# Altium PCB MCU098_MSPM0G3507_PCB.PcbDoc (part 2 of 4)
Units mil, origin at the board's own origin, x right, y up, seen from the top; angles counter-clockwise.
Board outline 2310.03 x 4205.03 mil, 4 copper layers (Top Layer, VCC Layer, GND Layer, Bottom Layer), stack 62.4 mil thick; 260 components, 182 nets, 835 pads, 237 vias.
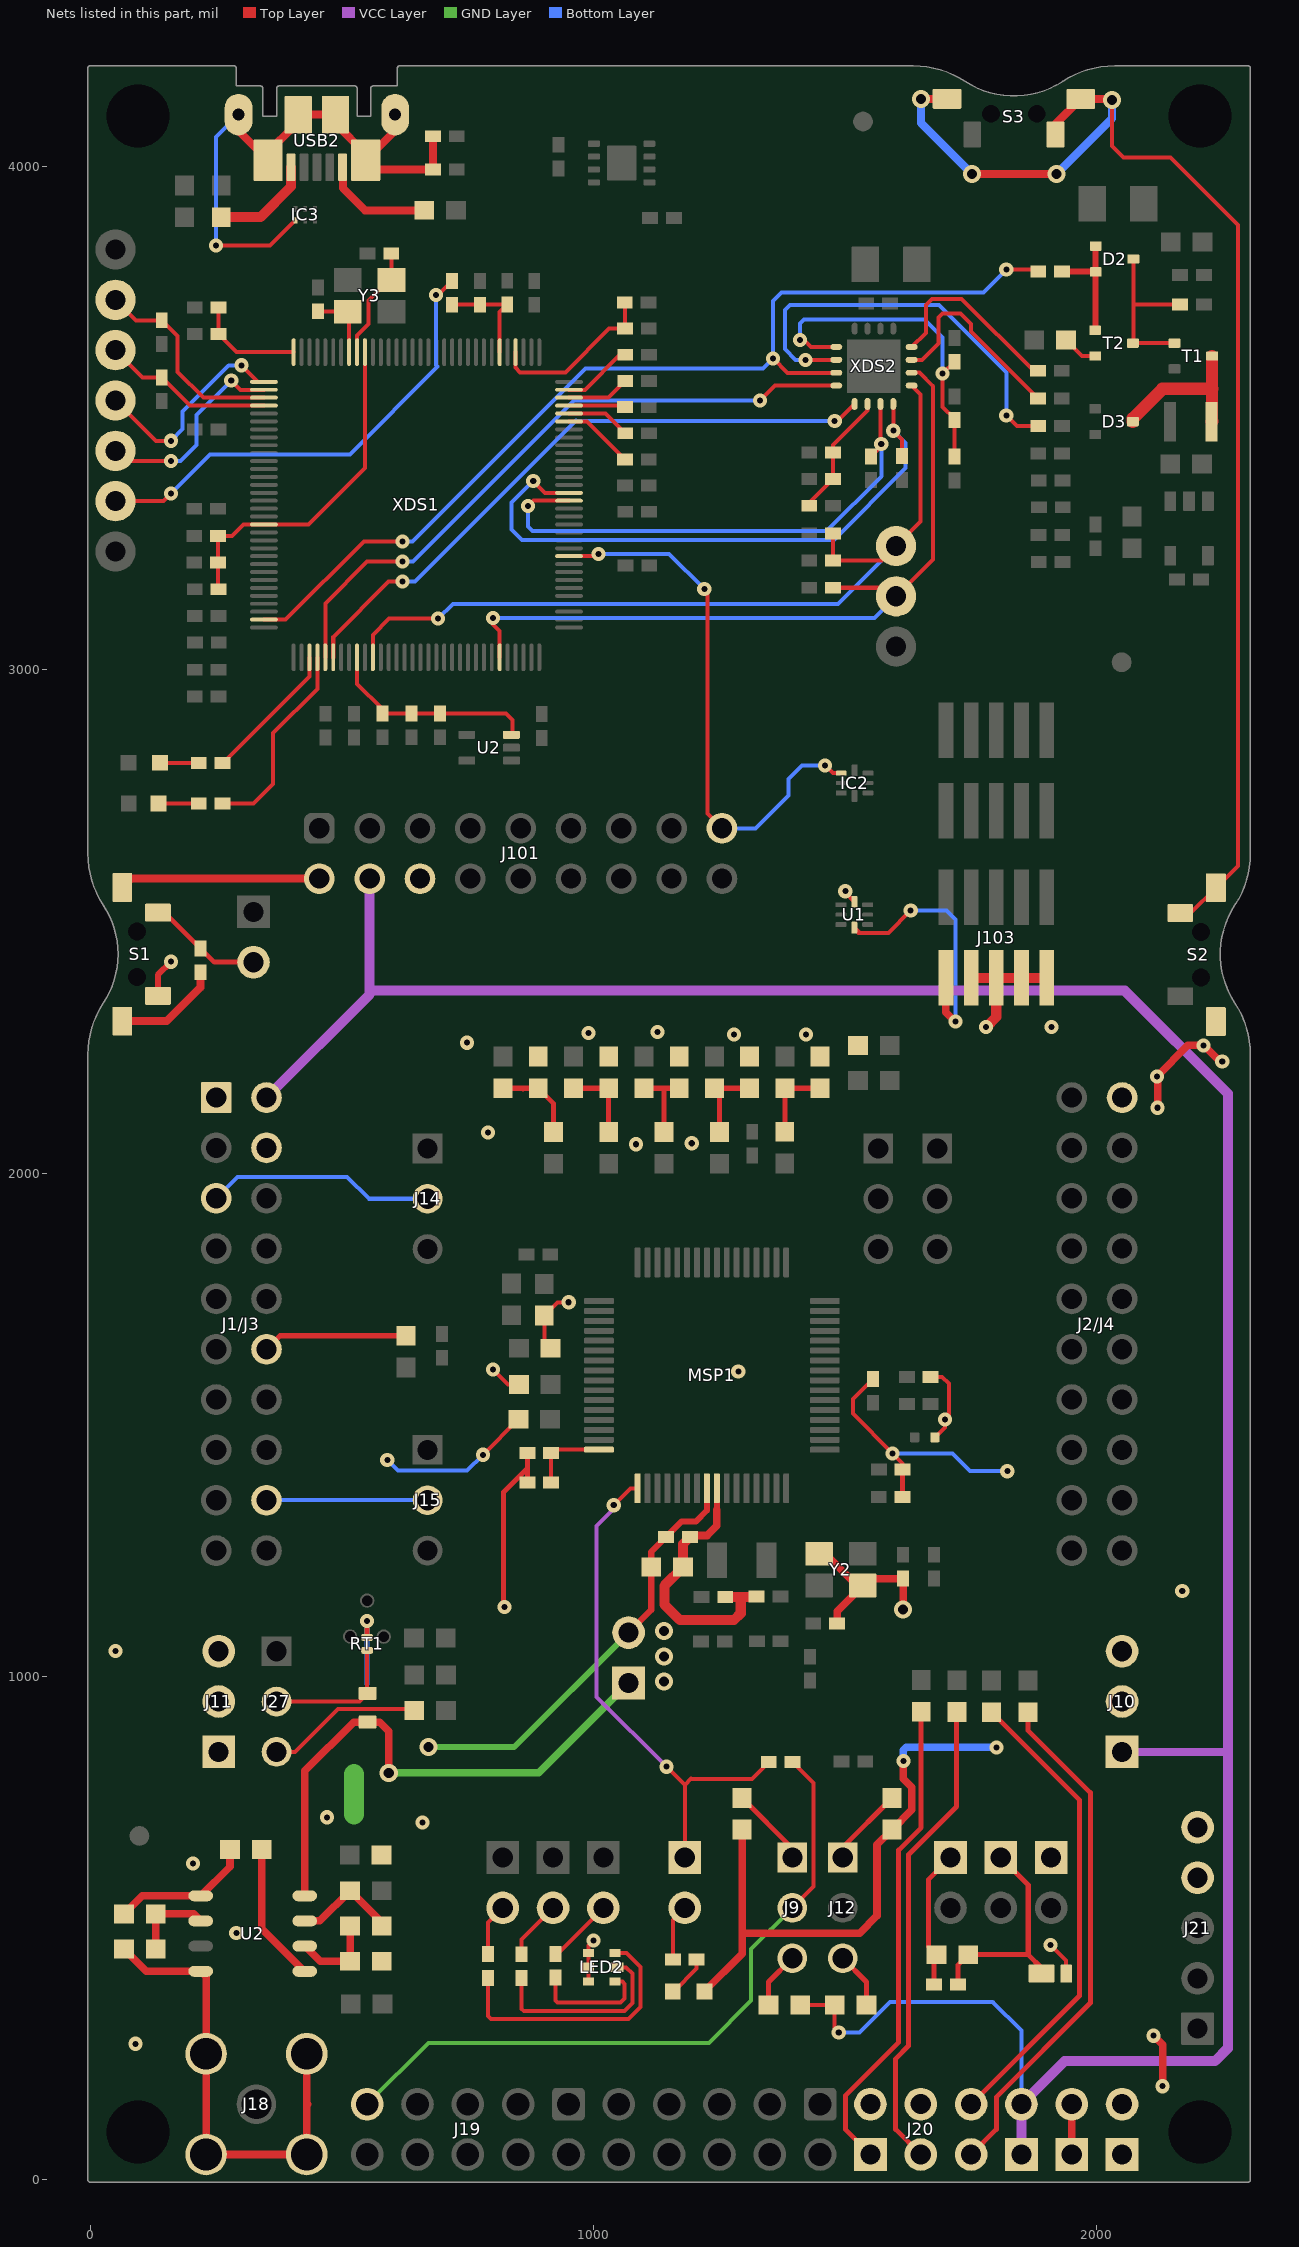
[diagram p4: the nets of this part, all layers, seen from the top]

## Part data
C1: library part CMP-0007304-1, "CAP, CERM, 10 uF, 6.3 V, +/- 20%, X5R, 0603", Cap_Case=0603, Manufacturer=MuRata, Supplier Part Number 1=490-7316-1-ND, TempCo=X5R, Tolerance_%=20%, Value1=Unknown, Value2=6.3V, ValueDisplayed=10uF
C2: library part CMP-0006614-2, "CAP, CERM, 0.1 uF, 50 V, +/- 20%, X5R, 0402", Cap_Case=0402, Manufacturer=MuRata, Supplier Part Number 1=GRM155R61H104ME14D-ND, TempCo=X5R, Tolerance_%=20%, Value1=Unknown, Value2=50V, ValueDisplayed=0.1uF
C3: library part CMP-0006551-2, "CAP, CERM, 0.47 uF, 6.3 V, +/- 10%, X5R, 0402", Cap_Case=0402, Manufacturer=MuRata, Supplier Part Number 1=490-3266-1-ND, TempCo=X5R, Tolerance_%=10%, Value1=Unknown, Value2=6.3V, ValueDisplayed=0.47uF
C4: library part CMP-0006614-2, "CAP, CERM, 0.1 uF, 50 V, +/- 20%, X5R, 0402", Cap_Case=0402, Manufacturer=MuRata, Supplier Part Number 1=GRM155R61H104ME14D-ND, TempCo=X5R, Tolerance_%=20%, Value1=Unknown, Value2=50V, ValueDisplayed=DNC
C5: library part CMP-0006388-2, "CAP, CERM, 47 pF, 25 V, +/- 5%, C0G/NP0, 0402", Cap_Case=0402, Manufacturer=MuRata, Supplier Part Number 1=81-GRM1555C1E470JA1D, TempCo=C0G/NP0, Tolerance_%=5%, Value1=Unknown, Value2=25V, ValueDisplayed=47pF
C6: library part CMP-0006590-2, "CAP, CERM, 0.01 uF, 16 V, +/- 10%, X5R, 0402", Cap_Case=0402, Manufacturer=MuRata, Supplier Part Number 1=GRM155R61C103KA01D-ND, TempCo=X5R, Tolerance_%=10%, Value1=Unknown, Value2=16V, ValueDisplayed=0.01uF
C7 C8: library part CMP-0007006-5, "CAP, CERM, 1 uF, 25 V, +/- 10%, X5R, 0603", Cap_Case=0603, Manufacturer=TDK, Supplier Part Number 1=445-5146-1-ND, TempCo=X5R, Tolerance_%=10%, Value1=Unknown, Value2=25V, ValueDisplayed=DNC
C9 C10 C11 C12: library part CMP-0006439-2, "CAP, CERM, 22 pF, 50 V, +/- 5%, C0G/NP0, 0402", Cap_Case=0402, Manufacturer=MuRata, Supplier Part Number 1=81-GRM1555C1H220JA1D, TempCo=C0G/NP0, Tolerance_%=5%, Value1=Unknown, Value2=50V, ValueDisplayed=22pF
C13 C17 C18 C20 C24 C27 C28 C33 C38 C39 C44: library part CMP-0006623-2, "CAP, CERM, 0.1 uF, 6.3 V, +/- 10%, X7R, 0402", Cap_Case=0402, Manufacturer=MuRata, Supplier Part Number 1=GRM155R70J104KA01D-ND, TempCo=X7R, Tolerance_%=10%, Value1=Unknown, Value2=6.3V, ValueDisplayed=0.1uF
C14 C15 C16 C22 C26: library part CMP-0006658-2, "CAP, CERM, 0.01 uF, 25 V, +/- 10%, X7R, 0402", Cap_Case=0402, Manufacturer=MuRata, Supplier Part Number 1=490-1312-1-ND, TempCo=X7R, Tolerance_%=10%, Value1=Unknown, Value2=25V, ValueDisplayed=0.01uF
C19 C21 C25 C55: library part CMP-0006276-2, "CAP, CERM, 1 uF, 25 V, +/- 10%, X5R, 0402", Cap_Case=0402, Manufacturer=TDK, Supplier Part Number 1=445-9066-1-ND, TempCo=X5R, Tolerance_%=10%, Value1=Unknown, Value2=25V, ValueDisplayed=1uF
C23 C56: library part CMP-0006543-2, "CAP, CERM, 2.2 uF, 6.3 V, +/- 10%, X5R, 0402", Cap_Case=0402, Manufacturer=MuRata, Supplier Part Number 1=81-GRM155R60J225KE5D, TempCo=X5R, Tolerance_%=10%, Value1=Unknown, Value2=6.3V, ValueDisplayed=2.2uF
C29 C30: library part CMP-0006415-2, "CAP, CERM, 12 pF, 50 V, +/- 5%, C0G/NP0, 0402", Cap_Case=0402, Manufacturer=MuRata, Supplier Part Number 1=14T3292, TempCo=C0G/NP0, Tolerance_%=5%, Value1=Unknown, Value2=50V, ValueDisplayed=12pF
C31 C34: library part CMP-0006454-1, "CAP, CERM, 33 pF, 50 V, +/- 5%, C0G/NP0, 0402", Cap_Case=0402, Manufacturer=MuRata, Supplier Part Number 1=81-GRM1555C1H330JA1D, TempCo=C0G/NP0, Tolerance_%=5%, Value1=Unknown, Value2=50V, ValueDisplayed=33pF
C32 C36: library part CMP-0011480-1, "CAP, TA, 4.7 uF, 16 V, +/- 10%, 4 ohm, SMD", Cap_Case=3216-18, Manufacturer=AVX, Supplier Part Number 1=478-3868-1-ND, Tolerance_%=10%, Value1="4 ohm", Value2=16V, ValueDisplayed=4.7uF
C35: library part CMP-0006354-2, "CAP, CERM, 1000 pF, 50 V, +/- 10%, X7R, AEC-Q200 Grade 1, 0402", Cap_Case=0402, Manufacturer=MuRata, Supplier Part Number 1=490-4761-1-ND, TempCo=X7R, Tolerance_%=10%, Value1=Unknown, Value2=50V, ValueDisplayed=1000pF
C37 C43: library part CMP-0007341-4, "CAP, CERM, 4.7 uF, 16 V, +/- 10%, X5R, 0603", Cap_Case=0603, Manufacturer=MuRata, Supplier Part Number 1=490-10481-1-ND, TempCo=X5R, Tolerance_%=10%, Value1=Unknown, Value2=16V, ValueDisplayed=4.7uF
C40: library part CMP-0007313-1, "CAP, CERM, 47 uF, 6.3 V, +/- 20%, X5R, 0603", Cap_Case=0603, Manufacturer=MuRata, TempCo=X5R, Tolerance_%=20%, Value1=Unknown, Value2=6.3V, ValueDisplayed=47uF
C41 C42: library part CMP-0006648-1, "CAP, CERM, 0.22 uF, 16 V, +/- 10%, X7R, 0402", Cap_Case=0402, Manufacturer=MuRata, Supplier Part Number 1=490-5418-1-ND, TempCo=X7R, Tolerance_%=10%, Value1=Unknown, Value2=16V, ValueDisplayed=0.22uF
C45 C46 C48 C49 C50 C51 C52 C53: library part CMP-0006906-5, "CAP, CERM, 2.2 uF, 10 V, +/- 10%, X5R, 0603", Cap_Case=0603, Manufacturer=Kemet, Supplier Part Number 1=399-4911-1-ND, TempCo=X5R, Tolerance_%=10%, Value1=Unknown, Value2=10V, ValueDisplayed=2.2uF
C47: library part CMP-0006970-1, "CAP, CERM, 82 pF, 50 V, +/- 10%, C0G/NP0, 0603", Cap_Case=0603, Manufacturer=Kemet, Supplier Part Number 1=399-1059-1-ND, TempCo=C0G/NP0, Tolerance_%=10%, Value1=Unknown, Value2=50V, ValueDisplayed=82pF
C54: library part CMP-0006688-2, "CAP, CERM, 3300 pF, 50 V, +/- 10%, X7R, 0402", Cap_Case=0402, Manufacturer=MuRata, Supplier Part Number 1=490-3248-1-ND, TempCo=X7R, Tolerance_%=10%, Value1=Unknown, Value2=50V, ValueDisplayed=3300pF
D1: library part CMP-0093192-1, "Photodiode PIN Chip 910nm Automotive 2-Pin Case 0805(2012Metric) T/R", Dark Current=0.001uA, Digikey Part Number=751-VEMD4110X01CT-ND, Forward Current=50mA, Manufacturer=Vishay, Mouser Part Number=78-VEMD4110X01, Operating Temperature Range="-40°C to +110°C", Reverse Breakdown Voltage=20V
D2 D3: library part CMP-0028883-1, "Diode, Schottky, 40 V, 0.12 A, AEC-Q101, SOT-323", Manufacturer=Nexperia, Supplier Part Number 1=568-7982-1-ND, Value1=0.12A, Value2=1V
FID1 FID2 FID3: library part CMP-0077181-1, "Fiducial mark.  There is nothing to buy or mount.", Manufacturer=N/A
H1 H2: library part CMP-0077978-1, "Spacer Support, Nylon 66", Manufacturer="Kang Yang"
IC1: library part CMP-0074212-1, "2.7-4V Dual In/Single Out MOSFET, 0.5A Main/0.1A Aux Input, Act-Low Enable, Comm. Temp., DBV0005A (SOT-23-5)", Alternate Manufacturer="Texas Instruments", Alternate PartNumber=TPS2102DBVT
IC2 U1: library part CMP-0043125-2, "Low-Capacitance + / - 15 kV ESD Protection Array for High-Speed Data Interfaces, 6 Channels, -40 to +85 degC, 8-pin UQFN (RSE), Green (RoHS & no Sb/Br)", Breakdown Voltage(Min)(V)=6, IO Capacitance(Typ)(pF)=1.6, IO Leakage Current(nA)=1, Manufacturer="Texas Instruments"
IC3: library part CMP-0043115-1, "ESD-Protection Array for High-Speed Data Interfaces, 4 Channels, -40 to +85 degC, 6-pin SON (DRY), Green (RoHS & no Sb/Br)", Breakdown Voltage(Min)(V)=6, IO Capacitance(Typ)(pF)=1.6, IO Leakage Current(nA)=1, Manufacturer="Texas Instruments"
IC4: library part CMP-0036329-3, "500mA, Adjustable, Low Quiescent Current, Low-Noise, High-PSRR, Single-Output LDO Regulator, DRB0008A (VSON-8)", Manufacturer="Texas Instruments", Operating Temperature Range="-40 to 125 C", Rating=Catalog
J1 J2 J3 J4 J5 J6 J7 J8 J13 J22 J23 J24: library part CMP-0055312-1, "Header, 100mil, 2x1, Tin, TH", Manufacturer=Molex, Supplier Part Number 1=WM8072-ND
J1/J3: library part CMP-0003837-4, "Receptacle, 2.54mm, 10x2, Tin, TH", Alternate Manufacturer="Major League Electronics", Alternate PartNumber=CRD-081413-A-G, Manufacturer=Samtec, Supplier Part Number 1=SAM1204-10-ND
J2/J4: library part CMP-0078266-4, "Receptacle, 2.54mm, 10x2, Tin, TH", Alternate Manufacturer="Major League Electronics", Alternate PartNumber=CRD-081413-A-G, Manufacturer=Samtec, Supplier Part Number 1=SAM1204-10-ND
J9 J10 J11 J12 J14 J15 J25 J26 J27: library part CMP-0002338-1, "Header, 100mil, 3x1, Tin, TH", Color=Black, Current_A=3A, Manufacturer="Sullins Connector Solutions", Supplier Part Number 1=S1012E-03-ND, Voltage_V=1.8kV
J17 J19: library part CMP-0054806-2, "Header, 2.54 mm, 5x2, Gold, TH", Current_A=3A, Manufacturer="Wurth Elektronik", Supplier Part Number 1=732-2672-ND, Voltage_V=250V
J18: library part CMP-0054990-1, "SMA Straight PCB Socket Die Cast, 50 Ohm, TH", Manufacturer="TE Connectivity", Supplier Part Number 1=A97594-ND, ValueDisplayed=DNC
J20: library part CMP-0054565-2, "Header, 100mil, 3x2, Gold, TH", Color=Black, Current_A=3A, Manufacturer="Sullins Connector Solutions", Supplier Part Number 1=S2011E-03-ND, Voltage_V=1.8kV
J21: library part CMP-0075485-1, "Header, 100mil, 5x1, Gold, TH", Manufacturer=Samtec, Supplier Part Number 1=SAM8737-ND
J101: library part CMP-0054622-1, "Header, 2.54mm, 9x2, Tin, TH", Color=Black, Current_A=3A, Manufacturer="Sullins Connector Solutions", Supplier Part Number 1=S2012E-09-ND
J102 J103: library part CMP-0075634-1, "Header(Shrouded), 1.27mm, 5x2, Gold, SMT", Color=Black, Current_A=3.3A, Manufacturer=Samtec, Supplier Part Number 1=SAM8799-ND
L1: library part CMP-0059590-1, "Inductor, Wirewound, Ceramic, 2.2 uH, 0.89 A, 0.13 ohm, SMD", Manufacturer="Taiyo Yuden", Supplier Part Number 1=587-1618-1-ND, Value1="0.13 ohm", Value2=0.89A, ValueDisplayed=2.2uH
LED1 LED101: library part CMP-0002972-3, "LED, Red, SMD", Color=Red, Manufacturer="Stanley Electric Co., LTD", Power_TotalModule=57.5mW, Value1=0.0575W, Value2=1.7V
LED2: library part CMP-0074720-1, "LED, RGB, SMD", Color=RGB, Manufacturer=Everlight, Supplier Part Number 1=19-337/R6GHBHC-A01/2T-ND, Value1=W, Value2=3.8V
LED102: library part CMP-0002827-3, "LED, Green, SMD", Color=green, Manufacturer=Lite-On, Power_TotalModule=100mW, Value1=0.1W, Value2=2.1V
LOGO1: library part CMP-0074844-1
Logo2 Logo3: library part CMP-0074838-1, "Texas Instrument Corporate Signature"
Logo4: library part CMP-0074840-1, "ESD Susceptible Symbol"
Logo6: library part CMP-0074847-1, "FCC_disclaimer"
Logo7: library part CMP-0074769-1
MH1 MH2 MH3 MH4: library part CMP-0078424-2, "PCB Mounting Hole, No Pad", Manufacturer=Any, PartNumber=N/A
MSP1: library part CMP-0093960-1, "Mixed-Signal Microcontrollers With CAN-FD Interface LQFP64", Frequency_Fixed=80MHz, Manufacturer="Texas Instruments", Max Supply Voltage=3.6V, Min Supply Voltage=1.62V, Operating Temperature Range="-40°C to +125°C"
R1: library part CMP-0022292-1, "RES, 2.37 M, 1%, 0.1 W, 0603", Manufacturer=Vishay-Dale, Power_W=100mW, Supplier Part Number 1=541-2.37MHCT-ND, TempCo="100 ppm/C", Tolerance_%=1%, Value2=0.1W, Value_Code=2M37, ValueDisplayed=2.37M
R2 R14: library part CMP-0026935-1, "RES, 47 k, 5%, 0.063 W, 0402", Manufacturer=Vishay-Dale, Power_W=63mW, Supplier Part Number 1=541-47KJCT-ND, TempCo="200 ppm/C", Tolerance_%=5%, Value2=0.063W, Value_Code=47k0, ValueDisplayed=47k
R3 R61 R66 R67 R68 R70 R74: library part CMP-0025885-5, "RES, 0, 5%, 0.1 W, 0603", Manufacturer=Yageo, Power_W=100mW, Supplier Part Number 1=311-0.0GRCT-ND, TempCo="200 ppm/C", Tolerance_%=5%, Value2=0.1W, Value_Code=0000, ValueDisplayed=DNC
R4 R29 R30: library part CMP-0026934-2, "RES, 470, 5%, 0.063 W, 0402", Manufacturer=Vishay-Dale, Power_W=63mW, Supplier Part Number 1=541-470JCT-ND, TempCo="200 ppm/C", Tolerance_%=5%, Value2=0.063W, Value_Code=470R, ValueDisplayed=470
R5: library part CMP-0026878-1, "RES, 220, 5%, 0.063 W, 0402", Manufacturer=Vishay-Dale, Power_W=63mW, Supplier Part Number 1=541-220JCT-ND, TempCo="200 ppm/C", Tolerance_%=5%, Value2=0.063W, Value_Code=220R, ValueDisplayed=220
R6 R7: library part CMP-0026906-1, "RES, 330, 5%, 0.063 W, 0402", Manufacturer=Vishay-Dale, Power_W=63mW, Supplier Part Number 1=541-330JCT-ND, TempCo="200 ppm/C", Tolerance_%=5%, Value2=0.063W, Value_Code=330R, ValueDisplayed=330
R8: library part CMP-0088648-1, "Res Thin Film 0402 100K Ohm 0.1% 1/16W ±25ppm/°C Molded SMD SMD Punched Carrier T/R", Digikey Part Number=P100KDCCT-ND, Manufacturer=Panasonic, Mouser Part Number=667-ERA-2AEB104X, Octopart Part Number=aea26725a1f47165, Operating Temperature Range="-55°C to +155°C", Power_W=63mW, TempCo=25ppm/°C, Tolerance_%=0.1%, Voltage=25V
R9 R10 R11 R15 R17 R20 R22: library part CMP-0027004-2, "RES, 0, 5%, 0.063 W, 0402", Manufacturer="Yageo America", Power_W=63mW, Supplier Part Number 1=311-0.0JRCT-ND, TempCo="200 ppm/C", Tolerance_%=5%, Value2=0.063W, Value_Code=0000, ValueDisplayed=DNC
R12 R16: library part CMP-0025927-5, "RES, 4.7 k, 5%, 0.1 W, 0603", Manufacturer=Yageo, Power_W=100mW, Supplier Part Number 1=311-4.7KGRCT-ND, TempCo="100 ppm/C", Tolerance_%=5%, Value2=0.1W, Value_Code=4k70, ValueDisplayed=4.7k
R13 R19: library part CMP-0026886-1, "RES, 270, 5%, 0.063 W, 0402", Manufacturer=Vishay-Dale, Power_W=63mW, Supplier Part Number 1=541-270JCT-ND, TempCo="200 ppm/C", Tolerance_%=5%, Value2=0.063W, Value_Code=270R, ValueDisplayed=270
R18 R21: library part CMP-0025906-5, "RES, 2.2 k, 5%, 0.1 W, 0603", Manufacturer=Yageo, PartNumber=RC0603JR-072K2L, Power_W=100mW, Supplier Part Number 1=311-2.2KGRCT-ND, TempCo="100 ppm/C", Tolerance_%=5%, Value2=0.1W, Value_Code=2k20, ValueDisplayed=2.2k
R23: library part CMP-0027004-2, "RES, 0, 5%, 0.063 W, 0402", Manufacturer="Yageo America", Power_W=63mW, Supplier Part Number 1=311-0.0JRCT-ND, TempCo="200 ppm/C", Tolerance_%=5%, Value2=0.063W, Value_Code=0000
R24 R25 R26 R34: library part CMP-0026852-1, "RES, 1.0 k, 5%, 0.063 W, 0402", Manufacturer=Vishay-Dale, Power_W=63mW, Supplier Part Number 1=541-1.0KJCT-ND, TempCo="200 ppm/C", Tolerance_%=5%, Value2=0.063W, Value_Code=1k00, ValueDisplayed=1.0k
R27: library part CMP-0026852-1, "RES, 1.0 k, 5%, 0.063 W, 0402", Manufacturer=Vishay-Dale, Power_W=63mW, Supplier Part Number 1=541-1.0KJCT-ND, TempCo="200 ppm/C", Tolerance_%=5%, Value2=0.063W, Value_Code=1k00, ValueDisplayed=DNC
R28: library part CMP-0026824-3, "RES, 100, 5%, 0.063 W, AEC-Q200 Grade 0, 0402", Manufacturer=Vishay-Dale, Power_W=63mW, Supplier Part Number 1=541-100JCT-ND, TempCo="200 ppm/C", Tolerance_%=5%, Value2=0.063W, Value_Code=100R, ValueDisplayed=100
R31 R91 R92: library part CMP-0026825-4, "RES, 10 k, 5%, 0.063 W, 0402", Manufacturer=Vishay-Dale, Power_W=63mW, Supplier Part Number 1=541-10KJCT-ND, TempCo="200 ppm/C", Tolerance_%=5%, Value2=0.063W, Value_Code=10k0, ValueDisplayed=10k
R32: library part CMP-0026413-2, "RES, 4.87 k, 1%, 0.063 W, AEC-Q200 Grade 0, 0402", Manufacturer=Vishay-Dale, Power_W=63mW, Supplier Part Number 1=541-4.87KLCT-ND, TempCo="100 ppm/C", Tolerance_%=1%, Value2=0.063W, Value_Code=4k87, ValueDisplayed=4.87k
R33: library part CMP-0026824-1, "RES, 100, 5%, 0.063 W, 0402", Manufacturer=Vishay-Dale, Power_W=63mW, Supplier Part Number 1=541-100JCT-ND, TempCo="200 ppm/C", Tolerance_%=5%, Value2=0.063W, Value_Code=100R, ValueDisplayed=100
R35: library part CMP-0026946-3, "RES, 51, 5%, 0.063 W, AEC-Q200 Grade 0, 0402", Manufacturer=Vishay-Dale, Power_W=63mW, Supplier Part Number 1=541-51JCT-ND, TempCo="200 ppm/C", Tolerance_%=5%, Value2=0.063W, Value_Code=51R0, ValueDisplayed=51
R36 R37 R43 R44 R51 R54 R88: library part CMP-0026728-1, "RES, 220 k, 1%, 0.0625 W, 0402", Manufacturer="Yageo America", Power_W=62.5mW, Supplier Part Number 1=311-220KLRCT-ND, TempCo="100 ppm/C", Tolerance_%=1%, Value2=0.0625W, Value_Code=220k
R38 R85: library part CMP-0026695-1, "RES, 3.30 k, 1%, 0.1 W, AEC-Q200 Grade 0, 0402", Manufacturer=Panasonic, Power_W=100mW, Supplier Part Number 1=P3.30KLCT-ND, TempCo="100 ppm/C", Tolerance_%=1%, Value2=0.1W, Value_Code=3k30, ValueDisplayed=3.30k
R39: library part CMP-0026231-1, "RES, 2.20 k, 1%, 0.063 W, 0402", Manufacturer=Vishay-Dale, Power_W=63mW, Supplier Part Number 1=541-2.20KLCT-ND, TempCo="100 ppm/C", Tolerance_%=1%, Value2=0.063W, Value_Code=2k20, ValueDisplayed=2.20k
R40: library part CMP-0026517-1, "RES, 6.81 k, 1%, 0.063 W, 0402", Manufacturer=Vishay-Dale, Power_W=63mW, Supplier Part Number 1=541-6.81KLCT-ND, TempCo="100 ppm/C", Tolerance_%=1%, Value2=0.063W, Value_Code=6k81, ValueDisplayed=6.81k
R41 R42: library part CMP-0026938-1, "RES, 4.7 k, 5%, 0.063 W, 0402", Manufacturer=Vishay-Dale, Power_W=63mW, Supplier Part Number 1=541-4.7KJCT-ND, TempCo="200 ppm/C", Tolerance_%=5%, Value2=0.063W, Value_Code=4k70, ValueDisplayed=4.7k
R45 R46 R49: library part CMP-0026737-1, "RES, 47.0 k, 1%, 0.0625 W, 0402", Manufacturer="Yageo America", Power_W=62.5mW, Supplier Part Number 1=311-47.0KLRCT-ND, TempCo="100 ppm/C", Tolerance_%=1%, Value2=0.0625W, Value_Code=47k0, ValueDisplayed=47.0k
R47: library part CMP-0026743-1, "RES, 820, 1%, 0.063 W, 0402", Manufacturer="Yageo America", Power_W=63mW, Supplier Part Number 1=311-820LRCT-ND, TempCo="100 ppm/C", Tolerance_%=1%, Value2=0.063W, Value_Code=820R, ValueDisplayed=820
R48: library part CMP-0026934-1, "RES, 470, 5%, 0.063 W, 0402", Manufacturer=Vishay-Dale, Power_W=63mW, Supplier Part Number 1=541-470JCT-ND, TempCo="200 ppm/C", Tolerance_%=5%, Value2=0.063W, Value_Code=470R, ValueDisplayed=470
R50 R53: library part CMP-0026728-1, "RES, 220 k, 1%, 0.0625 W, 0402", Manufacturer="Yageo America", Power_W=62.5mW, Supplier Part Number 1=311-220KLRCT-ND, TempCo="100 ppm/C", Tolerance_%=1%, Value2=0.0625W, Value_Code=220k, ValueDisplayed=DNC
R52 R55 R57 R58 R62 R63 R64 R65 R69 R71 R73 R75 R76 R77 R78 R79 R80 R81 R82 R83 R84 R86 R89: library part CMP-0025885-5, "RES, 0, 5%, 0.1 W, 0603", Manufacturer=Yageo, Power_W=100mW, Supplier Part Number 1=311-0.0GRCT-ND, TempCo="200 ppm/C", Tolerance_%=5%, Value2=0.1W, Value_Code=0000, ValueDisplayed=0
R56: library part CMP-0080084-1, "RES, 10.0 k, 0.1%, 0.1 W, AEC-Q200 Grade 0, 1.6x0.8mm", Manufacturer=Panasonic, Power_W=100mW, Supplier Part Number 1=P10KBDCT-ND, TempCo="10 ppm/C", Tolerance_%=0.1%, Value2=0.1W, Value_Code=10k0, ValueDisplayed=10.0k
R59 R60: library part CMP-0026938-5, "RES, 4.7 k, 5%, 0.063 W, AEC-Q200 Grade 0, 0402", Manufacturer=Vishay-Dale, Power_W=63mW, Supplier Part Number 1=541-4.7KJCT-ND, TempCo="200 ppm/C", Tolerance_%=5%, Value2=0.063W, Value_Code=4k70, ValueDisplayed=DNC
R72: library part CMP-0022736-4, "RES, 100, 1%, 0.1 W, 0603", Manufacturer=Yageo, Power_W=100mW, Supplier Part Number 1=311-100HRCT-ND, TempCo="100 ppm/C", Tolerance_%=1%, Value2=0.1W, Value_Code=100R, ValueDisplayed=100
R87: library part CMP-0026731-1, "RES, 330 k, 1%, 0.0625 W, 0402", Manufacturer="Yageo America", Power_W=62.5mW, Supplier Part Number 1=311-330KLRCT-ND, TempCo="100 ppm/C", Tolerance_%=1%, Value2=0.0625W, Value_Code=330k
R90: library part CMP-0026100-1, "RES, 1.00 M, 1%, 0.063 W, 0402", Manufacturer=Vishay-Dale, Power_W=63mW, Supplier Part Number 1=541-1.00MLCT-ND, TempCo="100 ppm/C", Tolerance_%=1%, Value2=0.063W, Value_Code=1M00, ValueDisplayed=1.00M
RT1: library part CMP-0084565-1, "Thermistor, DEC0002A (X1SON-2)", Alternate Manufacturer="Texas Instruments", Alternate PartNumber=TMP6131DECR
S1 S2 S3: library part CMP-0002328-1, "Switch, SPST, 0.05 A, 12 VDC, SMD", CurrentRating_mA=50A, Manufacturer=Diptronics
SH-J1 SH-J2 SH-J3 SH-J4 SH-J5 SH-J6 SH-J7 SH-J8 SH-J9 SH-J10 SH-J11 SH-J12 SH-J13 SH-J14 SH-J15 SH-J16 SH-J17 SH-J18 SH-J19 SH-J20 SH-J21 SH-J22 SH-J23 SH-J24 SH-J25: library part CMP-0003623-3, "Shunt, 100mil, Gold plated, Black", Alternate Manufacturer=3M, Alternate PartNumber=969102-0000-DA, Manufacturer=Samtec, Supplier Part Number 1=SAM8858-ND
T1: library part CMP-0000035-1, "MOSFET, P-CH, -20 V, -0.82 A, SOT-323", Alternate Manufacturer=None, Manufacturer="Diodes Inc.", Supplier Part Number 1=DMG1013UW-7DICT-ND, Value1=0.7, Value2="0.622 nC"
T2: library part CMP-0000466-1, "Transistor, NPN, 45 V, 0.1 A, SOT-323", Manufacturer="NXP Semiconductor", Supplier Part Number 1=568-6076-1-ND, Value1="0.1 A", Value2=800
TP1 TP2 TP3 TP4 TP5 TP6 TP7 TP8 TP9 TP10: library part CMP-0055138-1, "Test Point, Miniature, Black, TH", Color=Black, Manufacturer=Keystone, Supplier Part Number 1=36-5001-ND
U2: library part CMP-0032790-2, "Precision Micropower Shunt Voltage Reference, 0.5% accuracy, 2.5 V, 15 ppm / degC, 15 mA, -40 to 85 degC, 5-pin SC70 (DCK), Green (RoHS & no Sb/Br)", Manufacturer="Texas Instruments", Rating=Catalog, Temp Coeff(Max)(ppm/ degree C)=100, Temp Coeff(Typ)(ppm/ degree C)=15
U2: library part CMP-0040798-2, "50 MHz, Low-Noise Single-Supply Rail-to-Rail Operational Amplifier, 2.2 to 5.5 V, -40 to 125 degC, 8-pin SOIC (D8), Green (RoHS & no Sb/Br)", Manufacturer="Texas Instruments", Total Supply Voltage(Max)(+5V is 5, +/-5V is 10)=5.5, Total Supply Voltage(Min)(+5V is 5, +/-5V is 10)=2.2
USB2: library part CMP-0055311-1, "Receptacle, USB 2.0, Micro B, 5 Position, R/A, SMT", Color=Black, Current_A=1.8A, Manufacturer=Molex, Supplier Part Number 1=WM11263CT-ND, Voltage_V=30V
XDS1: library part CMP-0077954-1, "MSP432E401YTPDT, PDT0128A (TQFP-128)", Alternate Manufacturer="Texas Instruments", Alternate PartNumber=MSP432E401YTPDT
XDS2: library part CMP-0039611-2, "MSP430G2x52, MSP430G2x12 Mixed Signal Microcontroller, RSA0016B (VQFN-16)", Alternate PartNumber=MSP430G2452IRSA16T, Frequency(MHz)=16, Manufacturer="Texas Instruments", Operating Temperature Range="-40 to 85 C", Rating=Catalog, Temp Sensor=Yes
Y1: library part CMP-0004693-2, "Crystal, 32.768 KHz, 12.5 pF, SMD", Frequency_Fixed=32.768kHz, Manufacturer=Epson
Y2: library part CMP-0004696-2, "Crystal, 48 MHz, 12pF, SMD", Frequency_Fixed=48MHz, Frequency Stability=+/-30ppm, Manufacturer=Epson, Supplier Part Number 1="FA-238 48.0000MB-W0-ND"
Y3: library part CMP-0004635-1, "Crystal, 16 MHz, 8pF, SMD", Frequency_Fixed=16MHz, Frequency Stability=+/-30ppm, Manufacturer=NDK, Supplier Part Number 1=644-1157-1-ND
ZZ2 ZZ3 ZZ4: library part AssemblyNote, Alternate Manufacturer=-

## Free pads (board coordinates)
  round 0 hole 21 slot 162 at 90 deg unplated: 1(516,1079.25) 1(583,1079)
  round 0 hole 21 slot 87 at 0 deg unplated: 1(550,1150.56)

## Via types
v1: diameter 28, hole 12, Top Layer to Bottom Layer, 211 vias
v2: diameter 36, hole 20, Top Layer to Bottom Layer, 17 vias
v3: diameter 19.68, hole 7.87, Top Layer to Bottom Layer, 9 vias

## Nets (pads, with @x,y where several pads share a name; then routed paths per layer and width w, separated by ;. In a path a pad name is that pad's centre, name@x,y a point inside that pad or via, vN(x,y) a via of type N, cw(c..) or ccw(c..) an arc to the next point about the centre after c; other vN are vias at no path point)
3.3VM: J13.1 R56.2 U2.8 | length 1096
  Top Layer w15: U2.8@426.01,563.99 426.01,812.06 523.15,909.21 R56.2@551,909.21 574.87,909.21 592.88,891.2 v2(592.88,808.35)
  GND Layer w15: v2(592.88,808.35) 890.72,808.35 J13.1@1069.38,987
3V3: C1.1 C2.1 J1/J3.1 J11.1 J13.2 J21.4 J22.1 J22.2 J101.6 J103.1 LED1.1 MSP1.40 R2.2 R18.2 R21.2 R59.1 R60.1 R66.1 S1.4 U1.8 | length 3942.6
  Top Layer w8: v1(779.81,1440.28) R66.1@850.5,1511 ; LED1.1@1218.31,374 LED1.1@1219.3,374.98 ; U1.8@1517.93,2487.9 1525.82,2480 1525.82,2477.01 1585.51,2477.01 v1(1630,2521.5) ; R2.2@1555,1591 1514.9,1550.9 1514.9,1522.1 v1(1594,1443) 1613.62,1423.38 R60.1@1613.62,1410.66
  Top Layer w10: R59.1@1613.62,1356.35 R60.1@1613.62,1410.66
  Top Layer w12: S1.4@134.34,2352.05 134.34,2393.76 v1(160.5,2419.92) ; J13.2@1069.38,1087 1114.5,1132.13 C1.1@1114.5,1217 1114.5,1247.47 C2.1@1144.03,1277 1175.03,1308 1203.65,1308 1225.16,1329.5 MSP1.40@1225.16,1373.59
  Top Layer w15: LED1.1@1220.28,374 1295,448.72 1295,490 ; R18.2@1295,695.5 1295,490 ; v1(1615.38,831.7) 1615.38,796.62 1632.2,779.8 1632.2,734.7 R21.2@1593,695.5 1563,665.5 1563,524 1529,490 1295,490 ; J103.1@1700,2387.88 1700,2320 v1(1719,2301) ; J22.1@1950,50 J22.2@1950,150 ; v1(2112.5,286) 2130.5,268 v1(2130.5,185.66) ; v1(2120.5,2129.75) 2120.5,2191.25 v1(2119.5,2192.25) 2180.78,2253.53 v1(2212.05,2253.53) 2243.59,2222 v1(2249,2222)
  GND Layer w12: v2(671.62,859.36) 841.74,859.36 J13.2@1069.38,1087
  Bottom Layer w8: v1(590,1429.73) 611.14,1408.59 748.12,1408.59 v1(779.81,1440.28) ; v1(1594,1443) 1712.61,1443 1747.97,1407.63 v1(1821.89,1407.63) ; v1(1630,2521.5) 1701.5,2521.5 1719,2504 v1(1719,2301)
  Bottom Layer w15: v1(1615.38,831.7) 1615.38,853.07 1621.31,859 v1(1800.45,859)
+5V: J1/J3.21 J10.1 J23.1 J23.2 J101.4 R12.2 R16.2 | length 5658.7
  Top Layer w8: R12.2@1410.5,347 R16.2@1479,347 1479,300 v1(1487,292)
  VCC Layer w16: J10.1@2050,850 2259,850 2260,849 ; 2259.28,552.72 2260,552
  VCC Layer w20: J1/J3.21@350,2150 555,2355 555,2362.49 ; J101.4@555,2585 555,2362.49 ; J23.1@1850,50 J23.2@1850,150 1936,236 2235,236 2260,261 2260,552 2260,849 2260,2158 2055.51,2362.49 555,2362.49
  Bottom Layer w8: v1(1487,292) 1528,292 1589,353 1793,353 1850,296 J23.2@1850,150
AVCCOUT: C31.1 R36.1 R37.2 XDS2.1 | length 692.2
  Top Layer w8: v1(1410,3655) 1418.48,3655 1432.09,3641.39 XDS2.1@1482.2,3641.39 ; R36.1@1717,3423.62 R37.2@1717,3496 1717,3498.89 1693.32,3522.58 v1(1693.32,3588.31) C31.1@1717,3612
  Bottom Layer w8: v1(1410,3655) 1410,3688 1418,3696 1657.64,3696 1693.32,3660.32 v1(1693.32,3588.31)
BSL_INVOKE: IC2.1 J101.17 XDS1.42 | length 1103.5
  Top Layer w8: XDS1.42@951.15,3225.64 1005.39,3225.64 v1(1009.88,3230.13) ; v1(1219.88,3160.34) 1225.91,3154.31 1225.91,2714.09 J101.17@1255,2685 ; v1(1460.08,2810) 1475.52,2794.56 IC2.1@1491.99,2794.56
  Bottom Layer w8: v1(1009.88,3230.13) 1150.09,3230.13 v1(1219.88,3160.34) ; J101.17@1255,2685 1321.53,2685 1387,2750.47 1387,2782.76 1414.24,2810 v1(1460.08,2810)
CANRX: J20.3 R65.1 | length 950.4
  Top Layer w10: J20.3@1650,50 1600,100 1600,240 1625.8,265.8 1625.8,645.8 1721,741 1721,928.42 R65.1@1721.84,929.25
CANTX: J20.1 R64.1 | length 975.9
  Top Layer w10: J20.1@1563,50 J20.1@1550,50 1500,100 1500,167 1606.03,273.03 1606.03,654.6 1650.84,699.4 R64.1@1650.84,929.76
DCDCCAL0: R39.1 XDS2.12 | length 382.2
  Top Layer w8: XDS2.12@1631.8,3641.39 1660,3669.58 1660,3725 1672,3737 1731,3737 1873.8,3594.2 R39.1@1882.76,3594.2
DCDCCAL1: R38.1 XDS2.2 | length 846.7
  Top Layer w8: v1(1421.09,3615.8) XDS2.2@1482.2,3615.8 ; v1(1819.88,3505) 1840.88,3484 R38.1@1883.38,3484
  Bottom Layer w8: v1(1421.09,3615.8) 1401.2,3615.8 1380.01,3636.99 1380.01,3715.01 1390,3725 1685.86,3725 1819.88,3590.97 v1(1819.88,3505)
DCDCCAL2: R40.1 XDS2.11 | length 398.5
  Top Layer w8: XDS2.11@1631.8,3615.8 1652.8,3615.8 1685,3648 1685,3700 1693,3708 1729,3708 1750,3687 1750,3671.76 R40.1@1882.76,3539
DCDCIO0: XDS1.5 XDS2.4 | length 1301.6
  Top Layer w8: XDS1.5@466.9,3024.85 466.9,3131.9 550,3215 v1(620,3215) ; v1(1330.35,3535) 1359.97,3564.61 XDS2.4@1482.2,3564.61
  Bottom Layer w8: v1(620,3215) 641.3,3215 961.3,3535 v1(1330.35,3535)
DCDCIO1: XDS1.6 XDS2.5 | length 1268.8
  Top Layer w8: XDS1.6@482.65,3024.85 482.65,3065.15 ; 482.77,3065.15 482.77,3065.27 592.5,3175 v1(620,3175) ; v1(1479,3494) 1484.42,3494 XDS2.5@1518.61,3528.2
  Bottom Layer w8: v1(620,3175) 645,3175 965,3495 966,3494 v1(1479,3494)
DCDCPULSE: R47.2 XDS1.127 XDS2.3 | length 2033.7
  Top Layer w8: XDS1.127@344.85,3099.65 388.15,3099.65 543.5,3255 v1(620,3255) ; v1@1356,3619 1385.08,3589.92 1481.91,3589.92 XDS2.3@1482.2,3590.2 ; v1(1819.88,3795) 1879.38,3795 R47.2@1883.38,3791
  Bottom Layer w8: v1(620,3255) 640,3255 984,3599 1336.53,3599 v1(1356,3618.47) 1356,3733 1373,3750 1774.88,3750 v1(1819.88,3795)
DCDCRST: C35.1 R45.1 TP1.1 XDS1.11 XDS2.9 | length 1694.9
  Top Layer w8: XDS1.11@561.39,3024.85 561.39,3069.39 593.5,3101.5 v1(691,3101.5) ; R45.1@1475.62,3271 C35.1@1475.62,3217 1572,3217 TP1.1@1601,3246 1649.75,3294.75 1649.75,3546.66 XDS2.9@1631.8,3564.61
  Bottom Layer w8: v1(691,3101.5) 720.4,3130.9 1485.9,3130.9 TP1.1@1601,3246
DCDCTEST: R46.2 TP3.1 XDS1.27 XDS2.10 | length 1535.8
  Top Layer w8: v1(800,3103) 800,3090.3 813.35,3076.95 XDS1.27@813.35,3024.85 ; R46.2@1475.62,3163 1584,3163 TP3.1@1601,3146 1674,3219 1674,3563.34 1647.13,3590.2 XDS2.10@1631.8,3590.2
  Bottom Layer w8: v1(800,3103) 1558,3103 TP3.1@1601,3146
GND: C1.2 C2.2 C3.2 C4.2 C6.2 C7.2 C9.1 C10.1 C11.1 C12.1 C45.2 C47.2 C48.2 C49.2 C50.2 C51.2 C52.2 D1.1 J1/J3.22 J2/J4.20 J3.1 J10.2 J10.3 J11.2 J11.3 J18.2 J18.3 J18.4 J18.5 J20.2 J20.4 J21.5 J24.1 J24.2 J101.2 J103.3 J103.5 J103.7 J103.9 LED2.1 LED2.2 LED2.3 MSP1.41 R3.1 R8.2 R14.1 R67.1 R68.1 R70.1 RT1.1 S1.1 S1.2 S2.1 S2.2 S2.4 S3.1 S3.2 S3.3 U1.4 U2.4@219.32,413.99 Y2.2 Y2.4 | length 6449.1
  Top Layer w8: v1(800,1610.07) 830.07,1580 R67.1@851.5,1580 ; C7.2@914.5,1652 902,1664.5 R3.1@902,1716.85 928.45,1743.3 v1(950.5,1743.3) ; LED2.3@989.43,393.46 LED2.1@989.43,450.54 989.43,464.97 v1(1000,475.54) ; v1(1500,2560) 1500,2557.01 U1.4@1517.93,2539.08 ; C6.2@1669.62,1595 1692.44,1595 1706,1581.44 1706,1518 v1(1698,1510) 1698,1494.82 R8.2@1678.18,1475 ; v1(1908,466) 1939,435 D1.1@1939,409.52 ; v2(2030,4132) 2030,4041 2053.13,4017.87 2146.29,4017.87 2280,3884.17 2280,2610.57 S2.2@2236.31,2566.87 2186.11,2516.68 S2.4@2165.44,2516.68
  Top Layer w10: RT1.1@550,1077.3 v1(550,1109.72) ; v1(823.03,1138) 821,1140.03 821,1365.84 868.38,1413.21 ; C3.2@868.38,1385.27 868.38,1413.21 ; C4.2@868.38,1444 868.38,1413.21
  Top Layer w12: 1244.84,1330.57 MSP1.41@1244.84,1373.59
  Top Layer w15: R70.1@67.02,457.99 111.02,413.99 U2.4@219.32,413.99 230,403.31 J18.2@230,250 J18.3@230,50 J18.4@430,50 430,147.97 ; J18.5@430,250 430,147.97 ; 432.03,150 430,147.97 ; C2.2@1191.28,1277 1191.28,1279.93 1225.93,1279.93 1244.84,1298.84 1244.84,1330.57 ; Y2.2@1448.05,1243.5 1460.5,1243.5 1523.5,1180.5 Y2.4@1534.66,1180.5 ; C10.1@1483.62,1105 1483.62,1129.46 Y2.4@1534.66,1180.5 ; v2(1615,1133) C12.1@1615,1194.38 1548.54,1194.38 Y2.4@1534.66,1180.5
  Top Layer w16: S1.2@63.47,2301.85 151.8,2301.85 219,2369.05 R14.1@219,2399 ; S1.1@63.47,2567.6 80.87,2585 J101.2@455,2585 ; v2(1650.69,4134.31) S3.2@1702.13,4134.31 ; v2@1752.32,3985.32 v2(1752,3985) v2(1920,3985) ; S3.3@1920,4061.12 S3.3@1917.68,4063.44 1917.68,4084.11 S3.1@1967.87,4134.31 v2@2030,4134.31
  Top Layer w20: C2.2@1191.28,1277 1177.5,1263.22 C1.2@1177.5,1217 1140.45,1179.95 1140.45,1142.82 1171.27,1112 1279,1112 1292.34,1125.34 1292.34,1158 ; C9.1@1261.62,1158 1292.34,1158 ; C11.1@1323.72,1158.65 1323.07,1158 1292.34,1158 ; J103.3@1750,2387.88 J103.5@1800,2387.88 ; v1(1779.88,2289.97) 1800,2310.09 J103.5@1800,2387.88 ; J103.9@1900,2387.88 J103.7@1850,2387.88 J103.5@1800,2387.88
  GND Layer w40: 523.59,805.5 524,726
  Bottom Layer w10: 550,984.75 v1(550,1109.72)
  Bottom Layer w16: v2(1650.69,4134.31) 1650.69,4086.31 v2(1752,3985) ; v2(1920,3985) 2030,4095 v2(2030,4132)
  other v1: 89.87,270 290,490.19 204.02,628 660,710.04 470.5,720 50,1050.25 2169.5,1170 1287.41,1606 1084.35,2057.25 1194.92,2059.25 789.77,2080.75 748.04,2259 1279.3,2275 1422.24,2275 990,2278 1126.96,2280.64 1909.91,2290
  other v2: 1140,989.5 1140,1039.75 1140,1090
HOSTSCL: R42.1 XDS1.49 XDS2.7 | length 1051.7
  Top Layer w8: v1(870,3325.09) 880.78,3335.87 XDS1.49@951.15,3335.87 ; R42.1@1551,3423.98 1569.8,3442.77 XDS2.7@1569.8,3528.2
  Bottom Layer w8: v1(870,3325.09) 870,3285 879,3276 1463,3276 1571.5,3384.5 v1(1571.5,3448.35)
HOSTSDA: R41.1 XDS1.50 XDS2.8 | length 1241.2
  Top Layer w8: v1(880,3375.35) 903.73,3351.62 XDS1.50@951.15,3351.62 ; XDS2.8@1595.39,3528.2 v1(1595.39,3475) 1613,3457.39 R41.1@1613,3424.62
  Bottom Layer w8: v1(880,3375.35) 837.08,3332.44 837.08,3278.92 858,3258 1477.15,3258 1620.02,3400.87 1620.02,3450.37 v1(1595.39,3475)
IRSTN: R33.1 TP9.1 | length 937.9
  Top Layer w8: TP9.1@50,3335 145,3335 v1(160,3350) ; v1(687,3745) 691.24,3745 R33.1@718.87,3772.62
  Bottom Layer w8: v1(160,3350) 238,3428 515.62,3428 690,3602.38 687,3605.38 v1(687,3745)
ITCK: R92.2 TP6.1 XDS1.100 | length 340.5
  Top Layer w8: TP6.1@50,3635 104,3581 R92.2@142,3581 198.15,3524.85 XDS1.100@344.85,3524.85
ITDI: TP8.1 XDS1.98 | length 411.7
  Top Layer w8: TP8.1@50,3435 70,3415 v1(160,3415) ; v1(280,3575) 298.65,3556.35 XDS1.98@344.85,3556.35
  Bottom Layer w8: v1(160,3415) 179,3415 211,3447 211,3506 v1(280,3575)
ITDO: TP7.1 XDS1.97 | length 424.3
  Top Layer w8: TP7.1@50,3535 130,3455 v1(160,3455) ; v1(300,3605) 332.91,3572.09 XDS1.97@344.85,3572.09
  Bottom Layer w8: v1(160,3455) 183,3478 183,3513 275,3605 v1(300,3605)
ITMS: R91.2 TP5.1 XDS1.99 | length 417.2
  Top Layer w8: TP5.1@50,3735 90.62,3694.38 R91.2@142,3694.38 173,3663.38 173,3592 224.4,3540.6 XDS1.99@344.85,3540.6
LINRX: J20.6 R63.1 | length 945.4
  Top Layer w10: J20.6@1750,150 1965,365 1965,754.59 R63.1@1790.84,928.76 R63.1@1787,924.92
LINTX: J20.5 R62.1 | length 1029.5
  Top Layer w10: J20.5@1750,50 1800,100 1800,164 1987,351 1987,768.73 1862.84,892.9 R62.1@1862.84,928.76 R62.1@1862,927.92
NetC3_1: C3.1 C4.1 MSP1.32 | length 156.3
  Top Layer w8: C3.1@915.62,1385.27 C4.1@915.62,1444 921.98,1450.36 MSP1.32@1010.59,1450.36
NetC5_1: C5.1 J1.1 R1.2 | length 279.6
  Top Layer w10: C5.1@1676.38,387.54 1676.38,441.87 R1.2@1681.5,447 1665,463.5 1665,596 J1.1@1709,640
NetC5_2: C5.2 D1.2 J2.1 R1.1 | length 451.1
  Top Layer w10: C5.2@1723.62,387.54 1723.62,426.13 R1.1@1744.5,447 1863.53,447 ; J2.1@1809,640 1863.53,585.47 1863.53,447 ; D1.2@1889.79,409.52 1889.79,420.74 1863.53,447
NetC13_1: C13.1 R28.2 XDS1.96 | length 217.1
  Top Layer w8: R28.2@254.62,3720 C13.1@254.62,3667 290.47,3631.15 XDS1.96@403.91,3631.15
NetC20_1: C20.1 R31.1 R33.2 XDS1.70 | length 209.4
  Top Layer w8: R33.2@718.87,3725.38 828,3725.38 813.35,3710.73 XDS1.70@813.35,3631.15
NetC23_1: C23.1 C24.1 C25.1 XDS1.87 XDS1.115 | length 684.7
  Top Layer w8: C25.1@254.62,3160 253.62,3161 C24.1@253.62,3213 C23.1@253.62,3266 281.37,3266 304,3288.63 XDS1.115@344.85,3288.63 433.63,3288.63 545.64,3400.64 XDS1.87@545.64,3631.15
NetC26_1: C26.1 C27.1 R34.1 U2.3@836.63,2870.75 XDS1.9 | length 425.8
  Top Layer w8: XDS1.9@529.89,3024.85 529.89,2972.11 580.4,2921.6 R34.1@580.4,2913.26 C26.1@638,2913.26 C27.1@695,2913.26 825.74,2913.26 838.79,2900.21 U2.3@838.79,2870.75
NetC28_1: C28.1 R35.1 XDS1.68 | length 340.6
  Top Layer w8: XDS1.68@844.85,3631.15 844.85,3600.15 854,3591 944,3591 1031,3678 C28.1@1062.38,3678 1062.38,3729.38 R35.1@1061.76,3730
NetC29_1: C29.1 XDS1.88 Y3.3 | length 227.2
  Top Layer w8: XDS1.88@529.89,3631.15 529.89,3664.05 553,3687.16 553,3734.17 593.33,3774.5 Y3.3@598.31,3774.5 598.31,3826.66 C29.1@598,3826.97
NetC30_1: C30.1 XDS1.89 Y3.1 | length 140.7
  Top Layer w8: C30.1@452.72,3712.38 453.6,3711.5 Y3.1@511.69,3711.5 514.14,3709.06 XDS1.89@514.14,3631.15
NetC34_1: C34.1 R43.1 R44.2 XDS2.6 | length 250.2
  Top Layer w8: R43.1@1428.38,3326 1428.38,3331.76 R44.2@1475.62,3379 C34.1@1475.62,3432 1475.62,3446.62 1544.2,3515.2 XDS2.6@1544.2,3528.2
NetC48_1: C48.1 R75.2 R76.1 | length 161.2
  Top Layer w10: R76.1@1250,2081.5 1250,2158.5 R75.2@1240,2168.5 1282.73,2168.5 C48.1@1310,2168.5
NetC49_1: C49.1 R77.2 R78.1 | length 157.4
  Top Layer w10: R77.2@1100,2168.5 1139,2168.5 ; R78.1@1140,2081.5 1140,2167.5 1139,2168.5 ; C49.1@1170,2168.5 1139,2168.5
NetC50_1: C50.1 R79.2 R80.1 | length 170.8
  Top Layer w10: R79.2@820,2168.5 859,2168.5 ; 860,2167.5 859,2168.5 ; R80.1@920,2081.5 920,2138.5 C50.1@890,2168.5 859,2168.5
NetC51_1: C51.1 R81.2 R82.1 | length 156.3
  Top Layer w10: R82.1@1379.84,2082.25 1379.84,2168.34 R81.2@1380,2168.5 C51.1@1450,2168.5
NetC52_1: C52.1 R83.2 R84.1 | length 157
  Top Layer w10: R83.2@960,2168.5 C52.1@1030,2168.5 R84.1@1030,2081.5
NetC54_1: C54.1 IC3.1 R90.2 USB2.6 USB2.7 USB2.8 USB2.9 USB2.10 USB2.11 | length 1198.2
  Top Layer w8: v1(250,3843) 357.14,3843 IC3.1@407.32,3893.17
  Top Layer w16: USB2.10@294.58,4103 294.58,4071.01 USB2.11@353.14,4012.45 353.14,4028.5 405,4080.35 405,4094.82 USB2.9@413.18,4103 USB2.8@487,4103 487,4085.31 547.04,4025.27 USB2.6@547.04,4012.45 ; USB2.7@605.6,4103 605.6,4071.01 USB2.6@547.04,4012.45 ; C54.1@680.76,4060 R90.2@680.76,3994 565.49,3994 USB2.6@547.04,4012.45
  Bottom Layer w8: v1(250,3843) 250,4058.42 USB2.10@294.58,4103
NetD2_1: D2.1 D2.2 R47.1 T2.1 | length 234.7
  Top Layer w12: R47.1@1930.62,3791 1997.14,3791 D2.2@1997.6,3790.54 ; T2.1@1996.6,3674.59 1997.6,3675.59 D2.2@1997.6,3790.54 ; D2.1@1997.6,3841.72 D2.2@1997.6,3790.54
NetD2_3: D2.3 R48.1 T1.1 T2.3 | length 343.5
  Top Layer w8: D2.3@2072.4,3816.13 2072.4,3727 ; T1.1@2154,3649 T2.3@2071.4,3649 2072.4,3650 2072.4,3727 ; R48.1@2165.38,3726 2073.4,3726 2072.4,3727
NetD3_3: D3.3 L1.1 T1.3 | length 318.9
  Top Layer w24: L1.1@2228.8,3494.06 2228.8,3558 T1.3@2228.8,3623.41
  Top Layer w25: D3.3@2071.4,3493 2071.4,3499.33 2130.07,3558 2228.8,3558 ; L1.1@2227.74,3493 L1.1@2228.8,3494.06
NetJ1/J3_3: J1/J3.3 J14.2 | length 455.5
  Bottom Layer w8: J1/J3.3@250,1950 292.39,1992.39 510.15,1992.39 553.54,1949 J14.2@670,1949
NetJ1/J3_26: J1/J3.26 R58.1 | length 288.1
  Top Layer w10: J1/J3.26@350,1650 376.8,1676.8 R58.1@627,1676.8
NetJ1/J3_29: J1/J3.29 J15.2 | length 320
  Bottom Layer w8: J1/J3.29@350,1350 J15.2@670,1350
NetJ4_2: J4.2 R4.1 | length 112.6
  Top Layer w8: R4.1@1157.38,437.26 1157.38,516.24 J4.2@1181.14,540
NetJ5_2: J5.2 R5.1 | length 104.1
  Top Layer w8: R5.1@790.16,448.05 790.16,510.78 J5.2@819.38,540
NetJ6_2: J6.2 R6.1 | length 117.8
  Top Layer w8: R6.1@857,448 857,477.62 J6.2@919.38,540
NetJ7_2: J7.2 R7.1 | length 133.2
  Top Layer w8: R7.1@924,448.62 928,448.62 J7.2@1019.38,540
NetJ8_2: J8.2 R14.2 S1.3 | length 230.6
  Top Layer w10: S1.3@134.34,2517.4 147.91,2517.4 246.35,2418.97 J8.2@324.12,2418.97
NetJ9_1: J9.1 R18.1 | length 159.9
  Top Layer w10: R18.1@1295,758.5 1394.88,658.62 J9.1@1394.88,640
NetJ9_3: J9.3 R12.1 | length 112.6
  Top Layer w10: R12.1@1347.5,347 1347.5,392.63 J9.3@1394.88,440
NetJ12_1: J12.1 R21.1 | length 159.1
  Top Layer w10: J12.1@1494.88,640 1494.88,660.37 R21.1@1593,758.5
NetJ12_3: J12.3 R16.1 | length 112.5
  Top Layer w10: J12.3@1494.88,440 1541.99,392.88 R16.1@1541.99,347
NetJ27_2: J27.2 R56.1 RT1.2 | length 273.6
  Top Layer w8: J27.2@370,950 534.71,950 R56.1@551,966.29 550,967.29 RT1.2@550,1051.7
NetJ27_3: J27.3 R57.2 | length 295.6
  Top Layer w8: J27.3@370,850 407,850 492.5,935.5 626.67,935.5 R57.2@629.17,933
NetLED1_2: LED1.2 R4.2 | length 82
  Top Layer w8: LED1.2@1159.26,374 1204.62,419.36 R4.2@1204.62,437.26
NetLED2_4: LED2.4 R5.2 | length 533.2
  Top Layer w8: R5.2@790.16,400.81 790.16,324.84 796,319 1069.36,319 1093,342.64 1093,423 1065.46,450.54 LED2.4@1042.57,450.54
NetLED2_5: LED2.5 R6.2 | length 386.4
  Top Layer w8: R6.2@857,400.76 857,339.49 861.62,334.87 1060.87,334.87 1077,351 1077,409.52 1064.52,422 LED2.5@1045.53,422 LED2.5@1046.53,421
NetLED2_6: LED2.6 R7.2 | length 237.9
  Top Layer w8: R7.2@924,401.38 924,356.38 928.38,352 1053.76,352 1061.76,360 1061.76,388.94 1057.24,393.46 LED2.6@1042.57,393.46
NetLED101_1: LED101.1 R29.1 | length 78.9
  Top Layer w8: LED101.1@136.65,2815.41 137.06,2815 R29.1@215.38,2815
NetLED102_1: LED102.1 R30.1 | length 79.9
  Top Layer w8: LED102.1@135.53,2734 R30.1@215.38,2734
NetR24_1: R24.1 XDS1.63 | length 140.4
  Top Layer w8: XDS1.63@951.15,3556.35 983.15,3556.35 1052.8,3626 R24.1@1062.75,3626
NetR25_1: R25.1 XDS1.62 | length 125.4
  Top Layer w8: XDS1.62@951.15,3540.6 1029.35,3540.6 R25.1@1062.75,3574
NetR26_1: R26.1 XDS1.61 | length 112.4
  Top Layer w8: XDS1.61@951.15,3524.85 1059.53,3524.85 R26.1@1062.38,3522
NetR27_1: R27.1 XDS1.60 | length 127.8
  Top Layer w8: XDS1.60@951.15,3509.1 1023.65,3509.1 R27.1@1062.75,3470
NetR29_2: R29.2 XDS1.3 | length 282.2
  Top Layer w8: R29.2@262.62,2815 263.91,2815 435.4,2986.5 XDS1.3@435.4,3024.85
NetR30_2: R30.2 XDS1.4 | length 404.9
  Top Layer w8: R30.2@262.62,2734 324,2734 363.31,2773.31 363.31,2874.31 451.15,2962.15 XDS1.4@451.15,3024.85
NetR32_2: R32.2 XDS1.59 | length 142.4
  Top Layer w8: XDS1.59@951.15,3493.35 987.02,3493.35 R32.2@1062.38,3418
NetR52_2: R52.2 T2.2 | length 71.4
  Top Layer w8: R52.2@1938.5,3655.41 1970.5,3623.41 T2.2@1996.6,3623.41
NetR68_2: R68.2 R69.1 U2.6 | length 172.4
  Top Layer w15: U2.6@426.01,463.99 426.84,463.99 456.84,433.99 R68.2@516.01,433.99 R69.1@516.01,503.99
NetR69_2: R69.2 R72.1 U2.7 | length 210.9
  Top Layer w15: U2.7@426.01,513.99 456.01,513.99 R72.1@516.01,573.99 579,511 R69.2@579,503.99
NetR70_2: R70.2 R71.1 U2.2@219.32,513.99 | length 165.1
  Top Layer w15: R70.2@130.01,457.99 R71.1@130.01,527.99 205.32,527.99 U2.2@219.32,513.99
NetR71_2: R71.2 R73.1 U2.1@219.32,563.99 | length 283.3
  Top Layer w15: R71.2@67.02,527.99 103.02,563.99 U2.1@219.32,563.99 277.51,622.19 R73.1@277.51,655.99
NetR73_2: R73.2 U2.5@426.01,413.99 | length 277.9
  Top Layer w15: R73.2@340.5,655.99 340.5,498.66 425.18,413.99 U2.5@426.01,413.99
NetR86_1: R86.1 USB2.5 | length 221.3
  Top Layer w16: USB2.5@501.27,3998.28 502.13,3997.42 502.13,3956.8 545.97,3912.96 R86.1@663.44,3912.96
NetR89_1: R89.1 USB2.1 | length 203.5
  Top Layer w16: USB2.1@398.05,3997.42 USB2.1@398.91,3998.28
  Top Layer w20: R89.1@260,3899.23 338,3899.23 398.91,3960.14 USB2.1@398.91,3998.28
PA0: J4.1 MSP1.33 R13.1 | length 1034
  Top Layer w8: v1(1040,1340.07) 1073.52,1373.59 MSP1.33@1087.36,1373.59 ; v1(1144.69,820.5) 1181.14,784.05 ; J4.1@1181.14,640 1181.14,784.05 ; R13.1@1348,830 1314.5,796.5 1193.84,796.5 1193.72,796.62 1181.14,784.05
  VCC Layer w8: v1(1040,1340.07) 1040,1333.33 1005.87,1299.2 1005.87,959.31 v1(1144.69,820.5)
PA0-: J9.2 J19.9 R13.2 | length 1391.1
  Top Layer w8: J9.2@1394.88,540 1437.13,582.25 1437.13,788.12 R13.2@1395.24,830
  GND Layer w8: J19.9@550,150 672,272 1229,272 1313,356 1313,458.12 J9.2@1394.88,540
